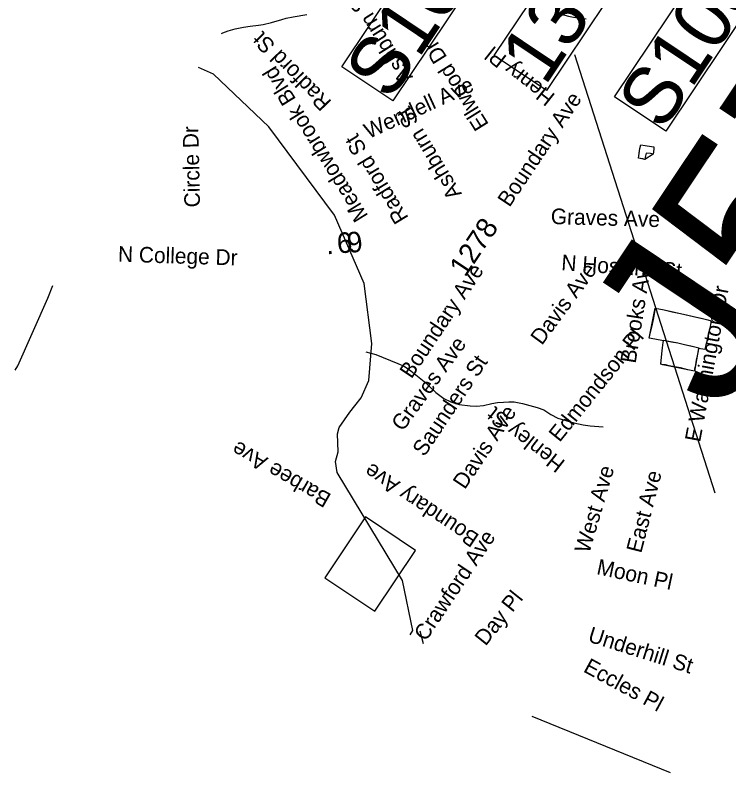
# Model space of a CAD drawing. Extents: x 1716282 to 1717158, y 799307 to 801078.
# Drawn here: x 1716503.1 to 1716566.1, y 799417.4 to 799484.2 of the extents above; entities that cross this region are included whole.
import ezdxf

# ---------------------------------------------------------------- set-up
doc = ezdxf.new("R2010")
doc.units = 0
for name, color, linetype in [('Exist Hydrographic Misc Water Feature', 7, 'Continuous'), ('Exist Road Non-System Structure Non-Sys Other Number Label', 7, 'Continuous'), ('Exist Road Non-System Type 51 Label', 7, 'Continuous'), ('Exist Road Primary US Structure Ovrhead Sign CELL', 7, 'Continuous'), ('Exist Road Secondary Mileage Tenths English Label', 7, 'Continuous'), ('Exist Road Secondary Structure NCDOT Private Pedestrian Number Label', 7, 'Continuous'), ('Exist Road Secondary Structure Standard Bridge Number Label', 7, 'Continuous'), ('Exist Road Secondary Type 51 Number Label', 7, 'Continuous')]:
    doc.layers.add(name, color=color, linetype=linetype)

msp = doc.modelspace()

# ---------------------------------------------------------------- linework, layer by layer
at = {"layer": 'Exist Hydrographic Misc Water Feature'}
for points in [[(1716521.336, 799482.56), (1716521.468, 799482.616), (1716521.937, 799482.787), (1716522.551, 799482.965), (1716523.276, 799483.104), (1716523.865, 799483.191), (1716524.599, 799483.29), (1716525.025, 799483.348), (1716525.742, 799483.525), (1716526.655, 799483.779), (1716527.051, 799483.897), (1716527.656, 799484.011), (1716528.865, 799484.238)], [(1716550.968, 799484.35), (1716551.939, 799484.074), (1716552.373, 799483.988), (1716552.758, 799483.936), (1716553.505, 799483.848)], [(1716537.993, 799429.561), (1716538.21, 799429.936), (1716537.301, 799434.367), (1716531.543, 799443.881), (1716531.409, 799444.84), (1716531.637, 799445.689), (1716531.57, 799447.285), (1716531.71, 799447.833), (1716532.676, 799449.191), (1716533.099, 799449.739), (1716533.659, 799450.462), (1716534.332, 799451.977), (1716534.597, 799455.246), (1716533.933, 799460.524), (1716531.302, 799466.56), (1716525.521, 799474.32), (1716520.641, 799478.966), (1716519.32, 799479.547)], [(1716558.311, 799472.729), (1716558.698, 799472.678), (1716559.083, 799472.624), (1716559.276, 799472.599), (1716559.468, 799472.572), (1716559.466, 799472.362), (1716559.405, 799471.913), (1716559.164, 799471.971), (1716558.803, 799472.009), (1716558.744, 799471.769), (1716558.676, 799471.462), (1716558.499, 799471.512), (1716558.114, 799471.566), (1716558.183, 799471.976), (1716558.244, 799472.425), (1716558.311, 799472.729)], [(1716558.311, 799472.729), (1716558.698, 799472.678), (1716559.276, 799472.599), (1716559.468, 799472.572), (1716559.466, 799472.362), (1716559.405, 799471.913), (1716558.676, 799471.462), (1716558.114, 799471.566), (1716558.244, 799472.425), (1716558.311, 799472.729)], [(1716503.149, 799452.882), (1716503.381, 799453.283), (1716506.022, 799459.225), (1716506.477, 799460.359)], [(1716560.329, 799455.472), (1716559.551, 799455.619), (1716559.054, 799455.714), (1716559.128, 799455.977), (1716559.29, 799456.676), (1716559.433, 799457.35), (1716559.527, 799457.848), (1716559.588, 799458.193), (1716559.597, 799458.361), (1716560.375, 799458.215), (1716561.098, 799458.039), (1716561.837, 799457.885), (1716562.471, 799457.734), (1716563.08, 799457.598), (1716563.756, 799457.454), (1716564.236, 799457.335), (1716564.525, 799457.245), (1716564.498, 799457.05), (1716564.398, 799456.595), (1716564.27, 799456.047), (1716564.16, 799455.525), (1716564.066, 799455.132), (1716563.957, 799454.716), (1716563.805, 799454.749), (1716563.42, 799454.802)], [(1716560.329, 799455.472), (1716559.551, 799455.619), (1716559.054, 799455.714), (1716559.597, 799458.361), (1716560.375, 799458.215), (1716563.756, 799457.454), (1716564.236, 799457.335), (1716564.525, 799457.245), (1716564.498, 799457.05), (1716564.398, 799456.595), (1716564.16, 799455.525), (1716564.066, 799455.132), (1716563.957, 799454.716), (1716563.42, 799454.802)], [(1716563.42, 799454.802), (1716563.377, 799454.586), (1716563.292, 799454.152), (1716563.216, 799453.783), (1716563.146, 799453.373), (1716563.044, 799453.019), (1716563.043, 799452.811), (1716562.458, 799452.931), (1716561.824, 799453.083), (1716561.285, 799453.169), (1716560.826, 799453.27), (1716560.499, 799453.355), (1716560.265, 799453.373), (1716560.089, 799453.424), (1716560.173, 799454.317), (1716560.234, 799454.87), (1716560.296, 799455.321), (1716560.329, 799455.472)], [(1716563.42, 799454.802), (1716563.043, 799452.811), (1716560.265, 799453.373), (1716560.089, 799453.424), (1716560.173, 799454.317), (1716560.234, 799454.87), (1716560.296, 799455.321), (1716560.329, 799455.472)], [(1716560.329, 799455.472), (1716560.338, 799455.537), (1716561.036, 799455.376), (1716561.575, 799455.289), (1716562.184, 799455.154), (1716562.731, 799455.027), (1716563.099, 799454.951), (1716563.429, 799454.866), (1716563.42, 799454.802)], [(1716560.329, 799455.472), (1716560.338, 799455.537), (1716561.575, 799455.289), (1716562.184, 799455.154), (1716563.099, 799454.951), (1716563.429, 799454.866), (1716563.42, 799454.802)], [(1716534.089, 799454.498), (1716534.947, 799454.262), (1716536.91, 799453.485), (1716537.454, 799453.253), (1716538.037, 799452.82), (1716539.36, 799451.775), (1716539.79, 799451.376), (1716540.252, 799450.921), (1716540.595, 799450.652), (1716540.954, 799450.405), (1716541.578, 799450.085), (1716542.308, 799449.868), (1716543.288, 799449.76), (1716543.819, 799449.714), (1716544.455, 799449.771), (1716545.173, 799449.947), (1716545.697, 799450.045), (1716546.212, 799450.082), (1716546.687, 799450.107), (1716547.145, 799450.11), (1716547.885, 799449.957), (1716549.184, 799449.597), (1716549.785, 799449.397), (1716550.383, 799448.987), (1716551.008, 799448.666), (1716552.403, 799448.24), (1716553.246, 799448.086), (1716553.848, 799447.99), (1716555.014, 799447.897)], [(1716538.84, 799429.929), (1716539.118, 799428.808)]]:
    msp.add_lwpolyline(points, dxfattribs=at)
at = {"layer": 'Exist Road Primary US Structure Ovrhead Sign CELL'}
for points in [[(1716531.957, 799479.624), (1716544.7, 799498.663), (1716549.209, 799495.645), (1716536.466, 799476.606)], [(1716556.007, 799476.96), (1716568.75, 799495.999), (1716573.259, 799492.981), (1716560.516, 799473.942)]]:
    msp.add_lwpolyline(points, close=True, dxfattribs=at)
at = {"layer": 'Exist Road Secondary Structure NCDOT Private Pedestrian Number Label'}
for p, q in [((1716530.461, 799434.601), (1716534.862, 799431.656)), ((1716560.955, 799417.408), (1716548.74, 799422.367))]:
    msp.add_line(p, q, dxfattribs=at)
msp.add_lwpolyline([(1716534.862, 799431.656), (1716538.444, 799437.007), (1716534.043, 799439.953), (1716530.461, 799434.601)], dxfattribs=at)
at = {"layer": 'Exist Road Secondary Structure Standard Bridge Number Label'}
msp.add_line((1716564.888, 799442.044), (1716552.515, 799480.667), dxfattribs=at)
msp.add_lwpolyline([(1716545.397, 799480.61), (1716550.592, 799488.372), (1716555.199, 799485.289), (1716550.004, 799477.527)], close=True, dxfattribs=at)

# ---------------------------------------------------------------- texts
at = {"layer": 'Exist Road Non-System Structure Non-Sys Other Number Label'}
msp.add_text('J572', height=15.223, rotation=56.20506, dxfattribs=at).set_placement((1716565.359, 799448.751))
at = {"layer": 'Exist Road Non-System Type 51 Label'}
for s, rotation, p in [('Ashburn St', 122.07806, (1716538.264, 799478.707)), ('Radford St', 134.5095, (1716531.121, 799476.558)), ('Ellwood Dr', 121.83908, (1716544.956, 799474.537)), ('Henry Pl', 141.65874, (1716550.851, 799477.131)), ('Meadowbrook Blvd', 121.77354, (1716534.32, 799466.491)), ('Wendell Ave', 24.65554, (1716534.326, 799473.244)), ('Boundary Ave', 56.20506, (1716546.74, 799467.181)), ('Ashburn St', 121.05254, (1716542.571, 799468.429)), ('Circle Dr', 91.22373, (1716519.456, 799467.243)), ('Radford St', 121.30373, (1716537.881, 799466.313)), ('Graves Ave', 358.34125, (1716550.372, 799465.769)), ('N College Dr', 358.22343, (1716512.203, 799462.445)), ('N Hoskins St', 355.93572, (1716551.281, 799461.705)), ('Brooks Ave', 81.01251, (1716557.864, 799453.436)), ('Boundary Ave', 56.20506, (1716538.099, 799452.067)), ('Davis Ave', 53.6781, (1716549.597, 799455.02)), ('E Washington Dr', 79.42616, (1716563.549, 799446.493)), ('Edmondson Pl', 51.13854, (1716551.16, 799446.477)), ('Graves Ave', 53.8833, (1716537.333, 799447.426)), ('Saunders St', 56.20506, (1716539.235, 799445.201)), ('Davis Ave', 56.20506, (1716542.803, 799442.315)), ('Henley St', 142.00211, (1716551.743, 799444.838)), ('Barbee Ave', 150.07227, (1716531.117, 799441.905)), ('Boundary Ave', 146.20506, (1716544.161, 799438.344)), ('West Ave', 73.56848, (1716553.774, 799436.686)), ('East Ave', 75.65546, (1716558.358, 799436.704)), ('Crawford Ave', 56.20506, (1716539.364, 799428.925)), ('Moon Pl', 347.99508, (1716554.355, 799434.924)), ('Day Pl', 51.42359, (1716544.632, 799428.522)), ('Underhill St', 342.53557, (1716553.578, 799428.999)), ('Eccles Pl', 331.4871, (1716553.175, 799426.362))]:
    msp.add_text(s, height=1.3775, rotation=rotation, dxfattribs=at).set_placement(p)
at = {"layer": 'Exist Road Primary US Structure Ovrhead Sign CELL'}
for s, p in [('S1087', (1716536.196, 799476.506)), ('S1088', (1716560.246, 799473.842))]:
    msp.add_text(s, height=5.075, rotation=56.20506, dxfattribs=at).set_placement(p)
at = {"layer": 'Exist Road Secondary Mileage Tenths English Label'}
for s, rotation, p in [('6', 4.53953, (1716531.591, 799463.166)), ('9', 8.54729, (1716532.567, 799463.184)), ('.', 4.53953, (1716530.613, 799463.089))]:
    msp.add_text(s, height=1.812, rotation=rotation, dxfattribs=at).set_placement(p)
at = {"layer": 'Exist Road Secondary Structure Standard Bridge Number Label'}
msp.add_text('13', height=5.075, rotation=56.20506, dxfattribs=at).set_placement((1716549.867, 799477.838))
at = {"layer": 'Exist Road Secondary Type 51 Number Label'}
msp.add_text('1278', height=1.8125, rotation=56.20506, dxfattribs=at).set_placement((1716542.833, 799461.017))

doc.saveas('drawing.dxf')
